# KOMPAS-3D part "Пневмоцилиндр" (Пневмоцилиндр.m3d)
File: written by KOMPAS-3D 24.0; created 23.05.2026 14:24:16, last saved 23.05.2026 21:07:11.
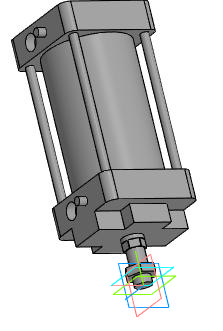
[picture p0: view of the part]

Document properties: Автор: R2D2; Полное имя файла: E:\Работа\Зайцев\GVKR1331E-1W-Fb-2P Задвижка шиберная DN.ru Ду50-300 Ру16-10-6\исходные материалы\DN80\Пневмоцилиндр.m3d

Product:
- Part/product: Пневмоцилиндр
    Масса: 17.894386

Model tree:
1. Эскиз:1
2. Элемент выдавливания:1
3. Смещенная плоскость:1
4. Эскиз:2
5. Элемент выдавливания:2
6. Эскиз:3  (with: Грань.Элемент выдавливания:1)
7. Элемент выдавливания:3
8. Эскиз:4  (with: Грань.Элемент выдавливания:3)
9. Элемент выдавливания:4  (with: Грань.Элемент выдавливания:3)
     Расстояние 2 = 9; Смещение 2 = 5
10. Эскиз:5  (with: Грань.Элемент выдавливания:3)
11. Элемент выдавливания:5
12. Эскиз:6  (with: Грань.Элемент выдавливания:5)
13. Элемент выдавливания:6
14. Эскиз:7  (with: Грань.Элемент выдавливания:6)
15. Элемент выдавливания:7
16. Эскиз:8  (with: Грань.Элемент выдавливания:7, Ребро.Элемент выдавливания:6)
17. Элемент выдавливания:8
18. Эскиз:9  (with: Грань.Элемент выдавливания:6, Вершина.Элемент выдавливания:8)
19. Элемент выдавливания:9  (with: Грань.Элемент выдавливания:8)
     Расстояние 1 = 158
20. Массив по концентрической сетке:1  (with: Элемент выдавливания:9, Эскиз:9)  (4 pattern instances)
     Шаг 2 = 360
21. Скругление:1  (with: Ребро.Элемент выдавливания:6, Ребро.Элемент выдавливания:8)
     Радиус = 10
22. Эскиз:10  (with: Грань.Элемент выдавливания:5, Ребро.Элемент выдавливания:6, Ребро.Элемент выдавливания:8)
23. Элемент выдавливания:10
24. Эскиз:11  (with: Грань.Элемент выдавливания:5, Ребро.Элемент выдавливания:10)
25. Элемент выдавливания:11
26. Эскиз:12  (with: Ребро.Элемент выдавливания:6, Ребро.Элемент выдавливания:5)
27. Элемент выдавливания:12

Expressions: k/2; c-2*g+x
